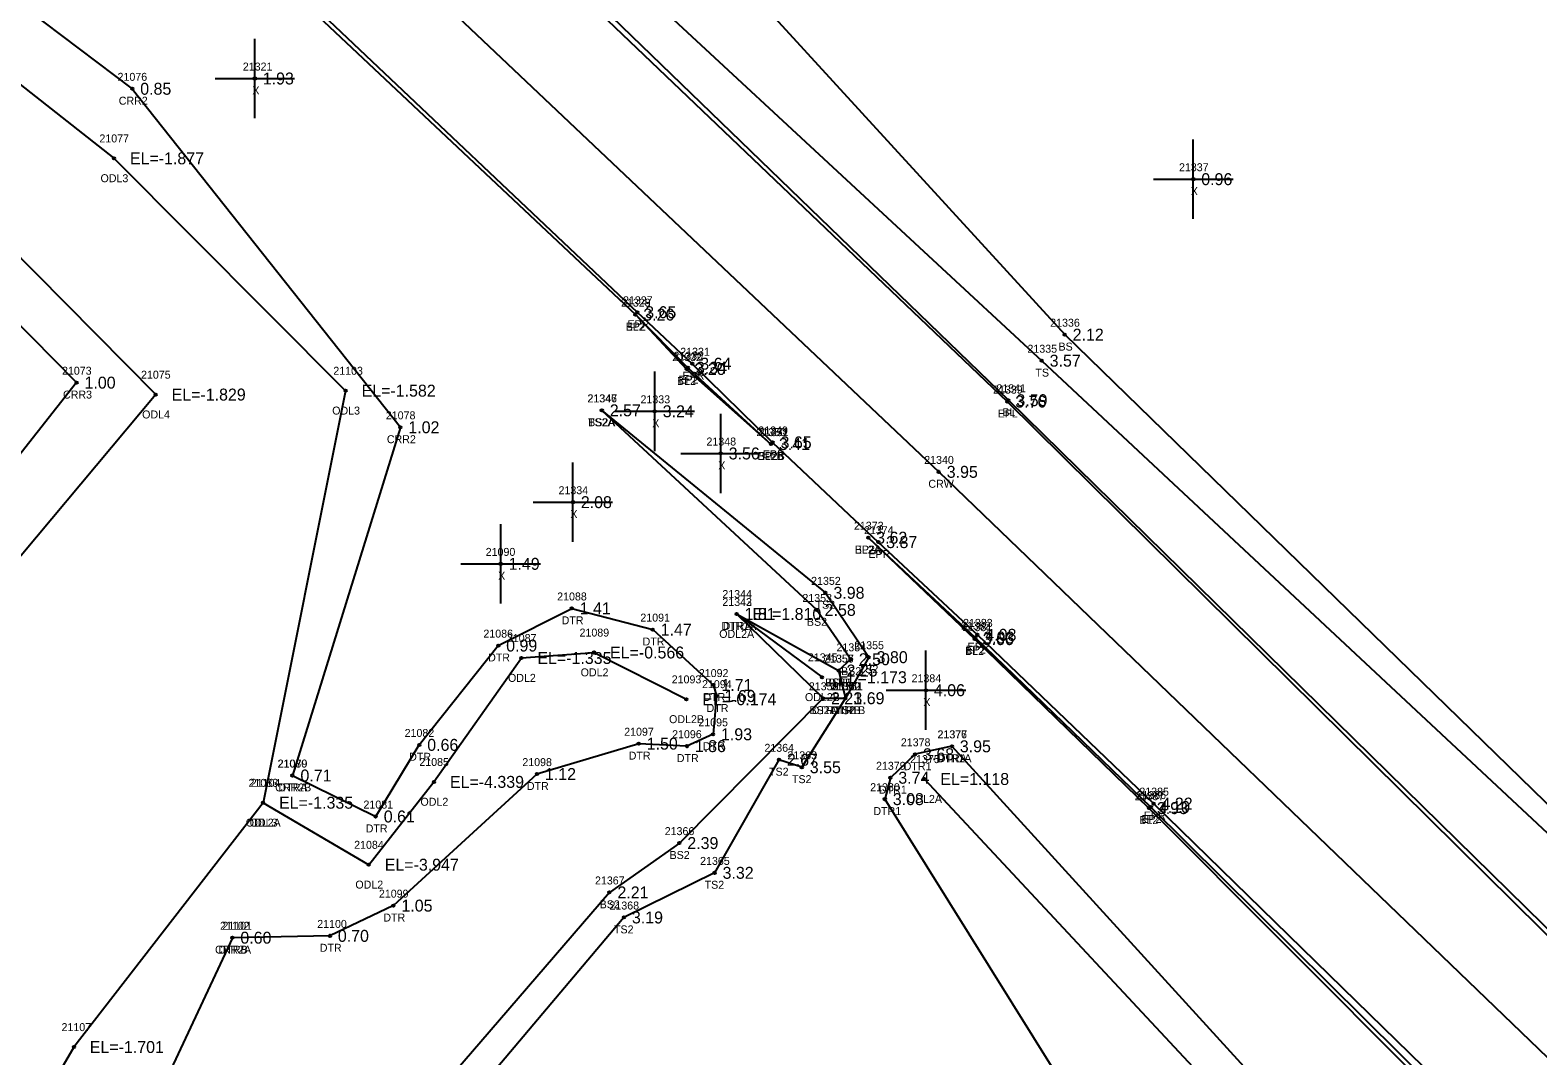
# Model space of a CAD drawing. Extents: x 2608745 to 2610333, y 641917 to 643463.
# Drawn here: x 2609885.8 to 2610075.3, y 642157.1 to 642286 of the extents above; entities that cross this region are included whole.
import ezdxf

# ---------------------------------------------------------------- set-up
doc = ezdxf.new("R2010")
doc.units = 0
for name, color, linetype in [('RD_DTM_BkLn1', 7, 'Continuous'), ('RD_DTM_BkLn2', 7, 'Continuous'), ('RD_DTM_BkLn_txCode', 7, 'Continuous'), ('RD_EX_H2O', 7, 'Continuous'), ('RD_EX_H2O_txCode', 7, 'Continuous'), ('RD_EX_Misc', 7, 'Continuous'), ('RD_EX_Misc_txCode', 7, 'Continuous'), ('RD_EX_Road', 7, 'Continuous'), ('RD_EX_Road_txCode', 7, 'Continuous'), ('RD_EX_TX_H2O_ELEV', 7, 'Continuous'), ('RD_EX_TX_Misc_ELEV', 7, 'Continuous'), ('RD_EX_TX_Road_ELEV', 7, 'Continuous'), ('RD_HC_Survey_ELEV', 7, 'Continuous'), ('RD_HC_Survey_txCode', 7, 'Continuous'), ('RD_SMD_Locator', 7, 'Continuous')]:
    doc.layers.add(name, color=color, linetype=linetype)

msp = doc.modelspace()

# ---------------------------------------------------------------- linework, layer by layer
at = {"layer": 'RD_DTM_BkLn1'}
for points in [[(2609568.4, 642647.43), (2609618.95, 642597.92), (2609693.89, 642525.38), (2609771.33, 642450.27), (2609850.26, 642373.69), (2609929.54, 642297.24), (2610000.01, 642230.49), (2610078.71, 642154.75), (2610156.09, 642080.44), (2610235.53, 642002.94), (2610263.59, 641975.77)], [(2609627.58, 642607.09), (2609630.23, 642605.37), (2609646.31, 642589.45), (2609703.16, 642535.02), (2609781.51, 642459.84), (2609859.44, 642383.51), (2609938.95, 642307.03), (2610008.76, 642239.49), (2610086.74, 642162.99), (2610105.31, 642145.89), (2610105.31, 642145.89), (2610140.26, 642113.1), (2610153.89, 642100.28), (2610164.72, 642089.82), (2610189.2, 642065.46)], [(2609638.64, 642561.68), (2609646.49, 642552.99), (2609655.41, 642544.68), (2609682.3, 642518.46), (2609696.97, 642504.35), (2609720.79, 642481.57), (2609738.97, 642465.02), (2609753.66, 642450.39), (2609762.69, 642441.83), (2609780.95, 642423.34), (2609796.2, 642407.99), (2609840.83, 642364.55), (2609897.27, 642310.29), (2609920.64, 642289.07), (2609961.88, 642250.25), (2609968.31, 642243.41), (2609978.92, 642233.98)], [(2609991.14, 642222.22), (2610004.52, 642209.47), (2610026.41, 642188.23), (2610060.62, 642153.9), (2610064.44, 642147.89), (2610069, 642144.94), (2610070.6, 642141.24), (2610070.91, 642133.58), (2610072.62, 642129.27)]]:
    msp.add_lwpolyline(points, dxfattribs=at)
at = {"layer": 'RD_DTM_BkLn2'}
for points in [[(2609582.66, 642657.54), (2609585.75, 642657.34), (2609622.53, 642623.2), (2609632.13, 642611.9), (2609647.4, 642591.36), (2609682.93, 642558.52), (2609706.14, 642537.77), (2609755.54, 642496.98), (2609786.05, 642464.88), (2609864.24, 642388.44), (2609941.53, 642310.67), (2610012.94, 642244.46), (2610082.83, 642179.18), (2610093.52, 642170.29)], [(2609755.54, 642496.98), (2609777.06, 642487.55), (2609794.23, 642472.67), (2609873.31, 642395.79), (2609950.73, 642318.92), (2610015.83, 642247.73), (2610085.46, 642180.03), (2610093.52, 642170.29)], [(2609957.67, 642238.22), (2609985.77, 642215.29), (2609991.2, 642207.2), (2609988.28, 642202.04), (2609982.8, 642193.37), (2609979.92, 642194.31), (2609971.84, 642180.1), (2609960.45, 642174.49), (2609936.49, 642146.07)], [(2609957.67, 642238.22), (2609984.67, 642213.14), (2609988.96, 642206.94), (2609987.41, 642205.52)], [(2609985.47, 642202.04), (2609967.41, 642183.84), (2609958.63, 642177.64), (2609933.35, 642148.28)]]:
    msp.add_lwpolyline(points, dxfattribs=at)
at = {"layer": 'RD_EX_H2O'}
msp.add_line((2609974.6, 642212.63), (2609985.35, 642204.68), dxfattribs=at)
for points in [[(2609550.15, 642638.19), (2609560.64, 642608.55), (2609596.58, 642544.67), (2609665.26, 642493.63), (2609726.89, 642435.57), (2609728.97, 642442.01), (2609745.88, 642433.78), (2609753.45, 642414.77), (2609764.24, 642411.87), (2609765.65, 642391.82), (2609764.35, 642384.35), (2609816.5, 642340.65), (2609898.67, 642278.63), (2609932.36, 642236.09), (2609918.8, 642192.33)], [(2609545.26, 642628.98), (2609557.91, 642602.6), (2609591.74, 642540.6), (2609658.48, 642494.06), (2609739.9, 642422.86), (2609760.07, 642378.85), (2609808.54, 642339.07), (2609896.37, 642269.89), (2609925.48, 642240.69), (2609915.11, 642188.91), (2609891.33, 642158.21), (2609835.84, 642063.03)], [(2609518.22, 642586.65), (2609536.97, 642578.99), (2609575.62, 642520.95), (2609643.94, 642461.12), (2609713.29, 642393.38), (2609797.14, 642314.29), (2609845.08, 642297.38), (2609901.61, 642240.2), (2609849.12, 642177.48), (2609793.89, 642090.6)], [(2609514.45, 642579.97), (2609534.32, 642569.3), (2609569.82, 642513.21), (2609640.11, 642458.03), (2609710.3, 642387.96), (2609794.99, 642310.91), (2609843.78, 642290.31), (2609891.67, 642241.7), (2609844.05, 642181.23), (2609787.66, 642090.39)], [(2609918.8, 642192.33), (2609929.27, 642187.18), (2609934.73, 642196.18), (2609944.65, 642208.66), (2609953.89, 642213.33), (2609964.06, 642210.67), (2609971.69, 642203.7), (2609972.09, 642202.31), (2609971.64, 642197.51), (2609968.36, 642196.02), (2609962.31, 642196.33), (2609949.52, 642192.51), (2609931.49, 642175.98), (2609923.5, 642172.18), (2609911.25, 642171.95)], [(2609974.6, 642212.63), (2609987.41, 642205.52), (2609988.28, 642202.04)], [(2609974.6, 642212.63), (2609985.47, 642202.04), (2609988.28, 642202.04)], [(2609915.11, 642188.91), (2609928.39, 642181.12), (2609936.58, 642191.53), (2609947.57, 642207.1), (2609956.7, 642207.79), (2609968.29, 642201.91)], [(2610001.65, 642196), (2609997.03, 642195), (2609993.92, 642192.05), (2609993.23, 642189.36), (2610025.09, 642138.24), (2610033.21, 642127.17), (2610029.91, 642117.96), (2610026.91, 642107.17), (2610030.12, 642088.07)], [(2610001.65, 642196), (2610043.53, 642150.08), (2610051.56, 642141.98), (2610057.33, 642129.72), (2610057.88, 642123.71), (2610050.62, 642108.28), (2610045.52, 642100), (2610039.29, 642092.45), (2610036.01, 642087.34), (2610033.47, 642085.84), (2610030.12, 642088.07)], [(2609998.2, 642191.89), (2610040.64, 642146.36), (2610047.86, 642138.57), (2610052.73, 642129.26), (2610054.42, 642123.75), (2610048.47, 642109.84), (2610036.4, 642092.37), (2610033.27, 642089.01)], [(2609911.25, 642171.95), (2609899.14, 642146.07), (2609837.93, 642059.5)]]:
    msp.add_lwpolyline(points, dxfattribs=at)
at = {"layer": 'RD_EX_Misc'}
for p, q in [((2609914.07, 642274.92), (2609914.07, 642284.92)), ((2609909.07, 642279.92), (2609919.07, 642279.92)), ((2610031.99, 642262.27), (2610031.99, 642272.27)), ((2610026.99, 642267.27), (2610036.99, 642267.27)), ((2609964.32, 642233.1), (2609964.32, 642243.1)), ((2609959.32, 642238.1), (2609969.32, 642238.1)), ((2609972.61, 642227.8), (2609972.61, 642237.8)), ((2609967.61, 642232.8), (2609977.61, 642232.8)), ((2609954.03, 642221.68), (2609954.03, 642231.68)), ((2609949.03, 642226.68), (2609959.03, 642226.68)), ((2609944.96, 642213.93), (2609944.96, 642223.93)), ((2609939.96, 642218.93), (2609949.96, 642218.93)), ((2609998.39, 642198.05), (2609998.39, 642208.05)), ((2609993.39, 642203.05), (2610003.39, 642203.05))]:
    msp.add_line(p, q, dxfattribs=at)
at = {"layer": 'RD_EX_Road'}
for points in [[(2609576.61, 642656.06), (2609590.88, 642642.24), (2609605.19, 642628.78), (2609627.58, 642607.09), (2609646.03, 642589.11), (2609702.18, 642534.04), (2609780.35, 642458.95), (2609858.79, 642382.83), (2609938.32, 642306.42), (2610008.62, 642239.32), (2610086.3, 642162.54), (2610164.18, 642089.49), (2610189.2, 642065.46), (2610214.78, 642040.19), (2610225.86, 642030.16), (2610226.32, 642028.39), (2610235.43, 642019.75), (2610260.23, 641995.63), (2610272.39, 641983.25)], [(2609841.8, 642365.54), (2609898.22, 642311.07), (2609921.04, 642289.43), (2609962.12, 642250.55), (2609969.04, 642244.08), (2609979.13, 642234.19), (2609992.4, 642221.66), (2610004.86, 642210.01), (2610027, 642188.8), (2610067.64, 642149.14), (2610070.8, 642146.19), (2610073.96, 642143.05), (2610116.51, 642103.01), (2610119.68, 642100.06), (2610135.09, 642085.92), (2610148.33, 642073.03), (2610165.14, 642055.61), (2610179.59, 642041.57), (2610196.49, 642024.71), (2610209.86, 642011.42), (2610228.39, 641994.06), (2610252.93, 641970.08), (2610256.35, 641966.74)], [(2609961.88, 642250.25), (2609968.49, 642243.57), (2609978.92, 642233.98)], [(2609991.14, 642222.22), (2610004.6, 642209.66), (2610026.66, 642188.37), (2610066.82, 642148.56), (2610069.65, 642145.36), (2610071.05, 642141.53), (2610071.68, 642138.94), (2610071.34, 642133.72), (2610072.62, 642129.27)]]:
    msp.add_lwpolyline(points, dxfattribs=at)
at = {"layer": 'RD_SMD_Locator'}
for centre in [(2609914.07, 642279.92), (2609898.67, 642278.63), (2609896.37, 642269.89), (2610031.99, 642267.27), (2609961.88, 642250.25), (2609961.88, 642250.25), (2609962.12, 642250.55), (2610015.83, 642247.73), (2609968.31, 642243.41), (2609968.49, 642243.57), (2609969.04, 642244.08), (2610012.94, 642244.46), (2609891.67, 642241.7), (2609901.61, 642240.2), (2609925.48, 642240.69), (2610008.62, 642239.32), (2610008.76, 642239.49), (2609957.67, 642238.22), (2609957.67, 642238.22), (2609964.32, 642238.1), (2609932.36, 642236.09), (2609978.92, 642233.98), (2609978.92, 642233.98), (2609979.13, 642234.19), (2609972.61, 642232.8), (2610000.01, 642230.49), (2609954.03, 642226.68), (2609991.14, 642222.22), (2609991.14, 642222.22), (2609992.4, 642221.66), (2609944.96, 642218.93), (2609985.77, 642215.29), (2609953.89, 642213.33), (2609984.67, 642213.14), (2609974.6, 642212.63), (2609974.6, 642212.63), (2609974.6, 642212.63), (2609964.06, 642210.67), (2610004.52, 642209.47), (2610004.6, 642209.66), (2610004.86, 642210.01), (2609944.65, 642208.66), (2609947.57, 642207.1), (2609956.7, 642207.79), (2609991.2, 642207.2), (2609987.41, 642205.52), (2609987.41, 642205.52), (2609988.96, 642206.94), (2609971.69, 642203.7), (2609985.35, 642204.68), (2609968.29, 642201.91), (2609972.09, 642202.31), (2609985.47, 642202.04), (2609985.47, 642202.04), (2609988.28, 642202.04), (2609988.28, 642202.04), (2609988.28, 642202.04), (2609998.39, 642203.05), (2609934.73, 642196.18), (2609962.31, 642196.33), (2609968.36, 642196.02), (2609971.64, 642197.51), (2610001.65, 642196), (2610001.65, 642196), (2609979.92, 642194.31), (2609997.03, 642195), (2609918.8, 642192.33), (2609918.8, 642192.33), (2609949.52, 642192.51), (2609982.8, 642193.37), (2609993.92, 642192.05), (2609936.58, 642191.53), (2609998.2, 642191.89), (2609915.11, 642188.91), (2609915.11, 642188.91), (2609993.23, 642189.36), (2610026.41, 642188.23), (2610026.66, 642188.37), (2610027, 642188.8), (2609929.27, 642187.18), (2609967.41, 642183.84), (2609928.39, 642181.12), (2609971.84, 642180.1), (2609958.63, 642177.64), (2609931.49, 642175.98), (2609960.45, 642174.49), (2609911.25, 642171.95), (2609911.25, 642171.95), (2609923.5, 642172.18), (2609891.33, 642158.21)]:
    msp.add_circle(centre, 0.15, dxfattribs=at)

# ---------------------------------------------------------------- texts
at = {"layer": 'RD_DTM_BkLn_txCode'}
for s, p in [('21328', (2609960.08, 642251.25)), ('BL2', (2609960.67, 642248.25)), ('21336', (2610014.01, 642248.73)), ('21332', (2609966.52, 642244.41)), ('21335', (2610011.15, 642245.46)), ('BS', (2610015.05, 642245.73)), ('TS', (2610012.15, 642242.46)), ('BL2', (2609967.11, 642241.41)), ('21341', (2610007.25, 642240.49)), ('21346', (2609955.85, 642239.22)), ('21347', (2609955.88, 642239.22)), ('BL', (2610008.01, 642237.49)), ('TS2A', (2609955.94, 642236.22)), ('BS2A', (2609955.95, 642236.22)), ('21351', (2609977.41, 642234.98)), ('BL2B', (2609977.24, 642231.98)), ('21372', (2609989.35, 642223.22)), ('BL2A', (2609989.45, 642220.22)), ('21352', (2609983.97, 642216.29)), ('21353', (2609982.87, 642214.14)), ('TS2', (2609984.52, 642213.29)), ('BS2', (2609983.44, 642211.14)), ('21381', (2610003, 642210.47)), ('21355', (2609989.4, 642208.2)), ('21357', (2609985.62, 642206.52)), ('21354', (2609987.16, 642207.94)), ('BL2', (2610003.31, 642207.47)), ('BS2', (2609987.73, 642204.94)), ('TS2', (2609989.96, 642205.2)), ('21358', (2609983.68, 642203.04)), ('BS2B', (2609985.71, 642203.52)), ('21362', (2609986.46, 642203.04)), ('BS2A', (2609983.76, 642200.04)), ('TS2', (2609987.04, 642200.04)), ('21364', (2609978.1, 642195.31)), ('21363', (2609980.99, 642194.37)), ('TS2', (2609978.68, 642192.31)), ('TS2', (2609981.56, 642191.37)), ('21387', (2610024.62, 642189.23)), ('BL2', (2610025.21, 642186.23)), ('21366', (2609965.57, 642184.84)), ('BS2', (2609966.18, 642181.84)), ('21365', (2609970.02, 642181.1)), ('21367', (2609956.81, 642178.64)), ('TS2', (2609970.59, 642178.1)), ('BS2', (2609957.4, 642175.64)), ('21368', (2609958.63, 642175.49)), ('TS2', (2609959.2, 642172.49))]:
    msp.add_text(s, height=1, dxfattribs=at).set_placement(p)
at = {"layer": 'RD_EX_H2O_txCode'}
for s, p in [('21076', (2609896.82, 642279.63)), ('CRR2', (2609896.97, 642276.63)), ('21077', (2609894.54, 642271.89)), ('ODL3', (2609894.68, 642266.89)), ('21073', (2609889.84, 642242.7)), ('21103', (2609923.93, 642242.69)), ('21075', (2609899.77, 642242.2)), ('CRR3', (2609889.97, 642239.7)), ('ODL4', (2609899.91, 642237.2)), ('ODL3', (2609923.79, 642237.69)), ('21078', (2609930.53, 642237.09)), ('CRR2', (2609930.66, 642234.09)), ('21088', (2609952.06, 642214.33)), ('21344', (2609972.81, 642214.63)), ('21342', (2609972.81, 642213.63)), ('21343', (2609972.81, 642213.63)), ('DTR', (2609952.62, 642211.33)), ('21091', (2609962.51, 642211.67)), ('DTR1A', (2609972.68, 642210.63)), ('DTRA', (2609972.85, 642210.63)), ('21086', (2609942.79, 642209.66)), ('21087', (2609945.74, 642209.1)), ('21089', (2609954.87, 642209.79)), ('DTR', (2609962.79, 642208.67)), ('ODL2A', (2609972.42, 642209.63)), ('DTR', (2609943.38, 642206.66)), ('21345', (2609983.56, 642206.68)), ('21356', (2609985.59, 642206.52)), ('ODL2', (2609955.01, 642204.79)), ('21092', (2609969.86, 642204.7)), ('ODL2', (2609945.88, 642204.1)), ('21093', (2609966.45, 642203.91)), ('21094', (2609970.26, 642203.31)), ('21359', (2609983.68, 642203.04)), ('DTR', (2609986.14, 642203.52)), ('21360', (2609986.42, 642203.04)), ('21361', (2609986.75, 642203.04)), ('DTR', (2609970.43, 642201.7)), ('ODL2B', (2609983.19, 642201.68)), ('ODL2B', (2609966.12, 642198.91)), ('DTR', (2609970.83, 642200.31)), ('DTR1', (2609984.04, 642200.04)), ('DTR1B', (2609986.38, 642200.04)), ('DTRB', (2609986.54, 642200.04)), ('21082', (2609932.89, 642197.18)), ('21097', (2609960.48, 642197.33)), ('21096', (2609966.5, 642197.02)), ('21095', (2609969.8, 642198.51)), ('21376', (2609999.83, 642197)), ('21377', (2609999.86, 642197)), ('DTR', (2609970.37, 642195.51)), ('21378', (2609995.24, 642196)), ('21080', (2609916.92, 642193.33)), ('21079', (2609916.96, 642193.33)), ('DTR', (2609933.46, 642194.18)), ('21085', (2609934.74, 642193.53)), ('21098', (2609947.68, 642193.51)), ('DTR', (2609961.05, 642194.33)), ('DTR', (2609967.09, 642194.02)), ('21379', (2609992.12, 642193.05)), ('DTR1', (2609995.6, 642193)), ('21375', (2609996.41, 642193.89)), ('DTR1A', (2609999.73, 642194)), ('DTRA', (2609999.89, 642194)), ('21083', (2609913.28, 642190.91)), ('21104', (2609913.56, 642190.91)), ('CRR2B', (2609916.62, 642190.33)), ('DTRA', (2609917.04, 642190.33)), ('DTR', (2609948.25, 642190.51)), ('21380', (2609991.39, 642190.36)), ('DTR1', (2609992.49, 642190.05)), ('21081', (2609927.72, 642188.18)), ('ODL2', (2609934.88, 642188.53)), ('DTR1', (2609991.79, 642187.36)), ('ODL2A', (2609996.02, 642188.89)), ('ODL2A', (2609912.93, 642185.91)), ('ODL3', (2609913.42, 642185.91)), ('DTR', (2609928, 642185.18)), ('21084', (2609926.55, 642183.12)), ('ODL2', (2609926.7, 642178.12)), ('21099', (2609929.66, 642176.98)), ('21102', (2609909.7, 642172.95)), ('21101', (2609909.99, 642172.95)), ('21100', (2609921.91, 642173.18)), ('DTR', (2609930.22, 642173.98)), ('CRR2A', (2609909.07, 642169.95)), ('DTRB', (2609909.51, 642169.95)), ('DTR', (2609922.23, 642170.18)), ('21107', (2609889.78, 642160.21))]:
    msp.add_text(s, height=1, dxfattribs=at).set_placement(p)
at = {"layer": 'RD_EX_Misc_txCode'}
for s, p in [('21321', (2609912.56, 642280.92)), ('X', (2609913.76, 642277.92)), ('21337', (2610030.19, 642268.27)), ('X', (2610031.67, 642265.27)), ('21333', (2609962.53, 642239.1)), ('X', (2609964.01, 642236.1)), ('21348', (2609970.82, 642233.8)), ('X', (2609972.3, 642230.8)), ('21334', (2609952.23, 642227.68)), ('X', (2609953.72, 642224.68)), ('21090', (2609943.08, 642219.93)), ('X', (2609944.64, 642216.93)), ('21384', (2609996.59, 642204.05)), ('X', (2609998.07, 642201.05))]:
    msp.add_text(s, height=1, dxfattribs=at).set_placement(p)
at = {"layer": 'RD_EX_Road_txCode'}
for s, p in [('21329', (2609960.08, 642251.25)), ('21327', (2609960.33, 642251.55)), ('EP2', (2609960.67, 642248.25)), ('EPR', (2609960.89, 642248.55)), ('21330', (2609966.66, 642244.57)), ('21331', (2609967.52, 642245.08)), ('EP2', (2609967.29, 642241.57)), ('EPR', (2609967.81, 642242.08)), ('21339', (2610006.82, 642240.32)), ('EPL', (2610007.41, 642237.32)), ('21350', (2609977.09, 642234.98)), ('21349', (2609977.33, 642235.19)), ('EP2B', (2609977.24, 642231.98)), ('EPR', (2609977.9, 642232.19)), ('21373', (2609989.35, 642223.22)), ('21374', (2609990.61, 642222.66)), ('EP2A', (2609989.45, 642220.22)), ('EPR', (2609991.17, 642219.66)), ('21382', (2610002.81, 642210.66)), ('21383', (2610003.06, 642211.01)), ('EP2', (2610003.4, 642207.66)), ('EPR', (2610003.63, 642208.01)), ('21386', (2610024.84, 642189.37)), ('21385', (2610025.21, 642189.8)), ('EP2', (2610025.46, 642186.37)), ('EPR', (2610025.77, 642186.8))]:
    msp.add_text(s, height=1, dxfattribs=at).set_placement(p)
at = {"layer": 'RD_EX_TX_H2O_ELEV'}
for s, p in [('0.85', (2609899.67, 642277.88)), ('EL=-1.877', (2609898.37, 642269.14)), ('1.00', (2609892.67, 642240.95)), ('EL=-1.582', (2609927.48, 642239.94)), ('EL=-1.829', (2609903.61, 642239.45)), ('1.02', (2609933.36, 642235.34)), ('1.41', (2609954.89, 642212.58)), ('1.81', (2609975.6, 642211.88)), ('1.81', (2609975.6, 642211.88)), ('EL=1.810', (2609976.6, 642211.88)), ('1.47', (2609965.06, 642209.92)), ('0.99', (2609945.65, 642207.91)), ('EL=-1.335', (2609949.57, 642206.35)), ('EL=-0.566', (2609958.7, 642207.04)), ('EL=1.173', (2609987.35, 642203.93)), ('2.25', (2609988.41, 642204.77)), ('1.71', (2609972.69, 642202.95)), ('EL=-0.174', (2609970.29, 642201.16)), ('1.69', (2609973.09, 642201.56)), ('2.21', (2609986.47, 642201.29)), ('3.69', (2609989.28, 642201.29)), ('3.69', (2609989.28, 642201.29)), ('1.93', (2609972.64, 642196.76)), ('0.66', (2609935.73, 642195.43)), ('1.50', (2609963.31, 642195.58)), ('1.86', (2609969.36, 642195.27)), ('3.95', (2610002.65, 642195.25)), ('3.95', (2610002.65, 642195.25)), ('3.68', (2609998.03, 642194.25)), ('0.71', (2609919.8, 642191.58)), ('0.71', (2609919.8, 642191.58)), ('EL=-4.339', (2609938.58, 642190.78)), ('1.12', (2609950.52, 642191.76)), ('3.74', (2609994.92, 642191.3)), ('EL=1.118', (2610000.2, 642191.14)), ('EL=-1.335', (2609917.11, 642188.16)), ('EL=-1.335', (2609917.11, 642188.16)), ('3.08', (2609994.23, 642188.61)), ('0.61', (2609930.27, 642186.43)), ('EL=-3.947', (2609930.39, 642180.37)), ('1.05', (2609932.49, 642175.23)), ('0.60', (2609912.25, 642171.2)), ('0.60', (2609912.25, 642171.2)), ('0.70', (2609924.5, 642171.43)), ('EL=-1.701', (2609893.33, 642157.46))]:
    msp.add_text(s, height=1.5, dxfattribs=at).set_placement(p)
at = {"layer": 'RD_EX_TX_Misc_ELEV'}
for s, p in [('1.93', (2609915.07, 642279.17)), ('0.96', (2610032.99, 642266.52)), ('3.26', (2609962.88, 642249.5)), ('2.12', (2610016.83, 642246.98)), ('3.57', (2610013.94, 642243.71)), ('3.20', (2609969.31, 642242.66)), ('3.59', (2610009.76, 642238.74)), ('2.57', (2609958.67, 642237.47)), ('2.57', (2609958.67, 642237.47)), ('3.24', (2609965.32, 642237.35)), ('3.41', (2609979.92, 642233.23)), ('3.56', (2609973.61, 642232.05)), ('2.08', (2609955.03, 642225.93)), ('3.62', (2609992.14, 642221.47)), ('1.49', (2609945.96, 642218.18)), ('3.98', (2609986.77, 642214.54)), ('2.58', (2609985.67, 642212.39)), ('3.66', (2610005.52, 642208.72)), ('2.50', (2609989.96, 642206.19)), ('3.80', (2609992.2, 642206.45)), ('2.25', (2609988.41, 642204.77)), ('4.06', (2609999.39, 642202.3)), ('2.21', (2609986.47, 642201.29)), ('3.69', (2609989.28, 642201.29)), ('2.67', (2609980.92, 642193.56)), ('3.55', (2609983.8, 642192.62)), ('3.93', (2610027.41, 642187.48)), ('2.39', (2609968.41, 642183.09)), ('3.32', (2609972.84, 642179.35)), ('2.21', (2609959.63, 642176.89)), ('3.19', (2609961.45, 642173.74))]:
    msp.add_text(s, height=1.5, dxfattribs=at).set_placement(p)
at = {"layer": 'RD_EX_TX_Road_ELEV'}
for s, p in [('3.26', (2609962.88, 642249.5)), ('3.65', (2609963.12, 642249.8)), ('3.34', (2609969.49, 642242.82)), ('3.64', (2609970.04, 642243.33)), ('3.76', (2610009.62, 642238.57)), ('3.41', (2609979.92, 642233.23)), ('3.65', (2609980.13, 642233.44)), ('3.62', (2609992.14, 642221.47)), ('3.87', (2609993.4, 642220.91)), ('3.93', (2610005.6, 642208.91)), ('4.08', (2610005.86, 642209.26)), ('4.10', (2610027.66, 642187.62)), ('4.22', (2610028, 642188.05))]:
    msp.add_text(s, height=1.5, dxfattribs=at).set_placement(p)
at = {"layer": 'RD_HC_Survey_ELEV'}
msp.add_text('3.95', height=1.5, dxfattribs=at).set_placement((2610001.01, 642229.74))
at = {"layer": 'RD_HC_Survey_txCode'}
for s, p in [('21340', (2609998.18, 642231.49)), ('CRW', (2609998.7, 642228.49))]:
    msp.add_text(s, height=1, dxfattribs=at).set_placement(p)

doc.saveas('drawing.dxf')
